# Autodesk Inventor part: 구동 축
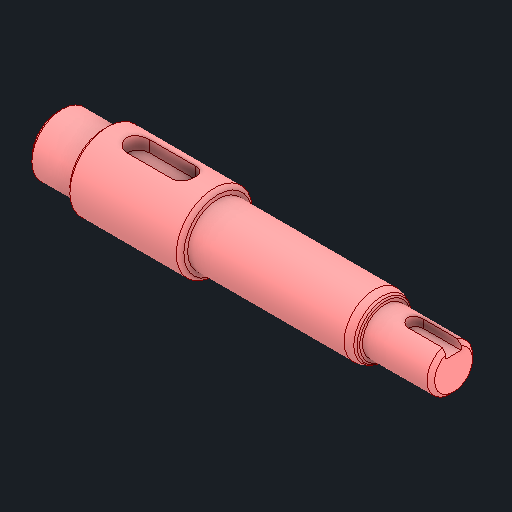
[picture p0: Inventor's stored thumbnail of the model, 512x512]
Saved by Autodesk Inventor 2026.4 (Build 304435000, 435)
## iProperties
Created: 2026-09
Part Number: 구동 축
Material: 강철, 탄소
Document SubType Name: Modeling
Designer: user
Density: 7.85 g/cm^3
Appearance: 기본값
Sending System: Autodesk Inventor 2027
Preprocessor: ST-DEVELOPER v20.1
Author: jhkim
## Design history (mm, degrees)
feature "솔리드1"
node "솔리드2"
